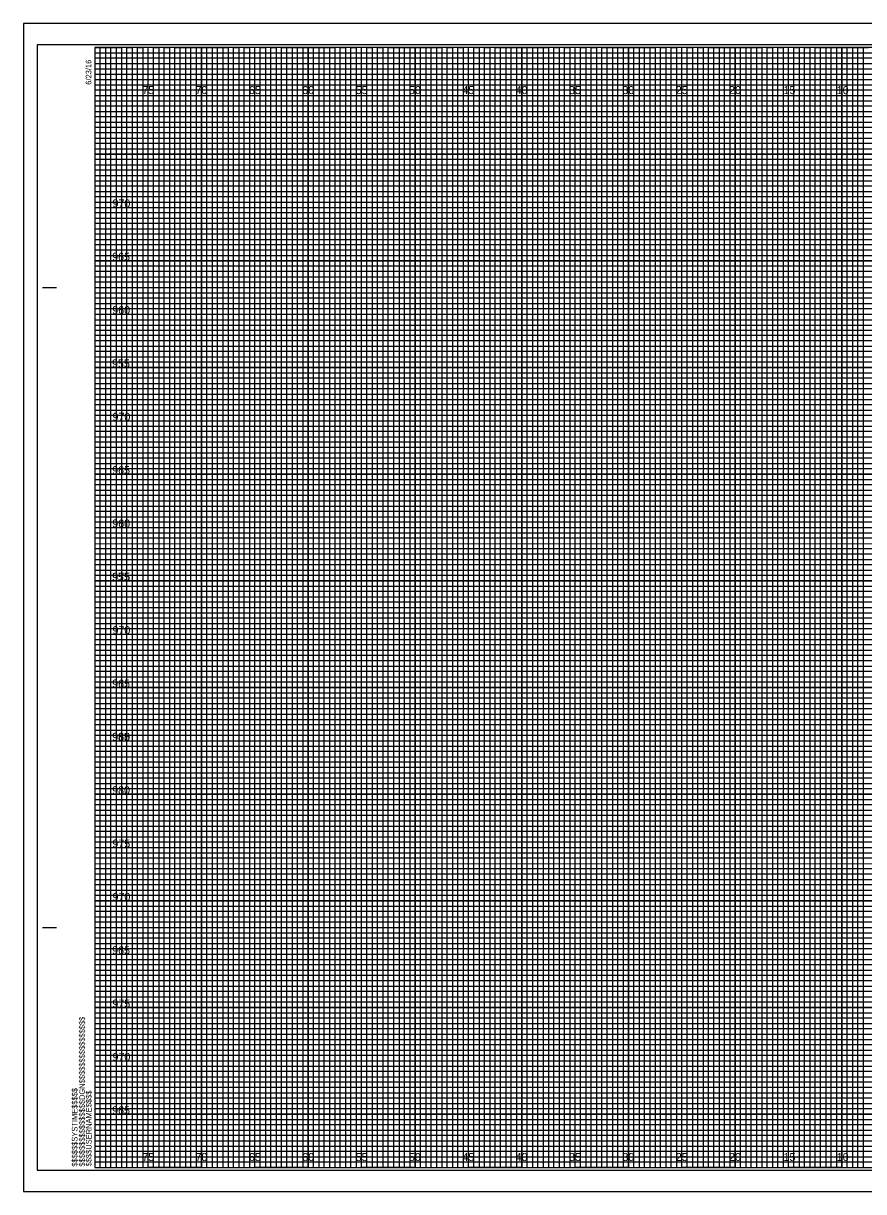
# Model space of a CAD drawing. Extents: x -7 to 162, y -2 to 107.
# Drawn here: x -6.7 to 72, y -2.3 to 107.3 of the extents above; entities that cross this region are included whole.
import ezdxf

# ---------------------------------------------------------------- set-up
doc = ezdxf.new("R2010")
doc.units = 0
for name, color, linetype in [('Prop XS Elevation Labels', 7, 'Continuous'), ('Prop XS Offset Labels', 7, 'Continuous'), ('Sheet Cross Section CELL', 7, 'Continuous'), ('Sheet Cross Section Grid Major CELL', 7, 'Continuous'), ('Sheet Cross Section Grid Middle CELL', 7, 'Continuous'), ('Sheet Cross Section Grid Minor 1 CELL', 7, 'Continuous'), ('Sheet Cross Section Grid Minor 2 CELL', 7, 'Continuous'), ('Sheet Cutting Line CELL', 7, 'Continuous'), ('Sheet DOT Grid CELL', 7, 'Continuous'), ('Sheet Plot Border Inside CELL', 7, 'Continuous'), ('Sheet Plot Border Outside CELL', 7, 'Continuous')]:
    doc.layers.add(name, color=color, linetype=linetype)

msp = doc.modelspace()

# ---------------------------------------------------------------- linework, layer by layer
at = {"layer": 'Sheet Cross Section CELL'}
for p, q in [((-4.9, 82.5), (-3.65, 82.5)), ((-4.85, 82.5), (-3.6, 82.5)), ((-4.9, 22.5), (-3.65, 22.5)), ((-4.85, 22.5), (-3.6, 22.5)), ((0, 0), (0, 0)), ((0, 0), (0, 0)), ((0, 0), (0, 0)), ((0, 0), (0, 0)), ((0, 0), (0, 0)), ((0, 0), (0, 0)), ((0, 0), (0, 0))]:
    msp.add_line(p, q, dxfattribs=at)
msp.add_lwpolyline([(160, 105), (0, 105), (0, 0), (160, 0)], close=True, dxfattribs=at)
at = {"layer": 'Sheet Cross Section Grid Major CELL'}
for p, q in [((5, 105), (0, 105)), ((5, 0), (5, 105)), ((15, 105), (10, 105)), ((10, 105), (10, 0)), ((15, 0), (15, 105)), ((25, 105), (20, 105)), ((20, 105), (20, 0)), ((25, 0), (25, 105)), ((35, 105), (30, 105)), ((30, 105), (30, 0)), ((35, 0), (35, 105)), ((45, 105), (40, 105)), ((40, 105), (40, 0)), ((45, 0), (45, 105)), ((55, 105), (50, 105)), ((50, 105), (50, 0)), ((55, 0), (55, 105)), ((65, 105), (60, 105)), ((60, 105), (60, 0)), ((65, 0), (65, 105)), ((75, 105), (70, 105)), ((70, 105), (70, 0)), ((10, 0), (5, 0)), ((20, 0), (15, 0)), ((30, 0), (25, 0)), ((40, 0), (35, 0)), ((50, 0), (45, 0)), ((60, 0), (55, 0)), ((70, 0), (65, 0))]:
    msp.add_line(p, q, dxfattribs=at)
for points in [[(0, 100), (160, 100), (160, 95), (0, 95)], [(0, 90), (160, 90), (160, 85), (0, 85)], [(0, 80), (160, 80), (160, 75), (0, 75)], [(0, 70), (160, 70), (160, 65), (0, 65)], [(0, 60), (160, 60), (160, 55), (0, 55)], [(0, 50), (160, 50), (160, 45), (0, 45)], [(0, 40), (160, 40), (160, 35), (0, 35)], [(0, 30), (160, 30), (160, 25), (0, 25)], [(0, 20), (160, 20), (160, 15), (0, 15)], [(0, 10), (160, 10), (160, 5), (0, 5)]]:
    msp.add_lwpolyline(points, dxfattribs=at)
at = {"layer": 'Sheet Cross Section Grid Middle CELL'}
for points in [[(0, 105), (2.5, 105), (2.5, 0), (7.5, 0), (7.5, 105), (12.5, 105), (12.5, 0), (17.5, 0), (17.5, 105), (22.5, 105), (22.5, 0), (27.5, 0), (27.5, 105), (32.5, 105), (32.5, 0), (37.5, 0), (37.5, 105), (42.5, 105), (42.5, 0), (47.5, 0), (47.5, 105), (52.5, 105), (52.5, 0), (57.5, 0), (57.5, 105), (62.5, 105), (62.5, 0), (67.5, 0), (67.5, 105), (72.5, 105)], [(0, 102.5), (137.5, 102.5)], [(0, 92.5), (160, 92.5), (160, 97.5), (0, 97.5)], [(0, 82.5), (160, 82.5), (160, 87.5), (0, 87.5)], [(0, 72.5), (160, 72.5), (160, 77.5), (0, 77.5)], [(0, 62.5), (160, 62.5), (160, 67.5), (0, 67.5)], [(0, 52.5), (160, 52.5), (160, 57.5), (0, 57.5)], [(0, 42.5), (160, 42.5), (160, 47.5), (0, 47.5)], [(0, 32.5), (160, 32.5), (160, 37.5), (0, 37.5)], [(0, 22.5), (160, 22.5), (160, 27.5), (0, 27.5)], [(0, 12.5), (160, 12.5), (160, 17.5), (0, 17.5)], [(0, 2.5), (160, 2.5), (160, 7.5), (0, 7.5)]]:
    msp.add_lwpolyline(points, dxfattribs=at)
at = {"layer": 'Sheet Cross Section Grid Minor 1 CELL'}
for p, q in [((0, 104.5), (130, 104.5)), ((130, 103.99), (0, 103.99)), ((0, 103.99), (0, 103.5)), ((0, 103.5), (130, 103.5)), ((130, 102.95), (0, 102.95)), ((0, 102.95), (0, 102)), ((0, 102), (160, 102))]:
    msp.add_line(p, q, dxfattribs=at)
for points in [[(0, 101.5), (135, 101.5), (160, 101.5), (160, 101), (0, 101)], [(0, 100.5), (160, 100.5), (160, 99.5), (0, 99.5)], [(0, 99), (160, 99), (160, 98.5), (0, 98.49)], [(0, 98), (160, 98), (160, 97), (0, 97)], [(0, 96.5), (160, 96.5), (160, 96), (0, 96)], [(0, 95.5), (160, 95.5), (160, 94.5), (0, 94.5)], [(0, 94), (160, 94), (160, 93.5), (0, 93.5)], [(0, 93), (160, 93), (160, 92), (0, 92)], [(0, 91.5), (160, 91.5), (160, 91), (0, 91)], [(0, 90.5), (160, 90.5), (160, 89.5), (0, 89.5)], [(0, 89), (160, 89), (160, 88.5), (0, 88.5)], [(0, 88), (160, 88), (160, 86.98), (160, 86.5), (160, 86), (0, 86)], [(0, 87), (160, 87), (160, 86.5), (0, 86.5)], [(0, 85.5), (160, 85.5), (160, 84.5), (0, 84.52)], [(0, 84.52), (160, 84.5), (160, 84), (0, 84)], [(0, 83.5), (160, 83.5), (160, 83), (0, 83)], [(0, 82), (160, 82), (160, 81.5), (0, 81.5)], [(0, 81), (160, 81), (160, 80.5), (0, 80.5)], [(-0.04, 79.45), (160, 79.45), (160, 78.94), (-0.04, 78.94)], [(0, 78.5), (160, 78.5), (160, 78), (0, 78)], [(0, 77), (160, 77), (160, 76.5), (0, 76.5)], [(0, 76), (160, 76), (160, 75.5), (0, 75.5)], [(0, 74.5), (160, 74.5), (160, 74), (0, 74)], [(0, 73.5), (160, 73.5), (160, 73), (0, 73)], [(0, 72), (160, 72), (160, 71.5), (0, 71.5)], [(0, 71), (160, 71), (160, 70.5), (0, 70.5)], [(0, 69.5), (160, 69.5), (160, 68.99), (0, 69)], [(0, 68.5), (160, 68.5), (160, 68), (0, 68)], [(0, 67), (160, 67), (160, 66.5), (0, 66.5)], [(0, 66), (160, 66), (160, 65.5), (0, 65.5)], [(0, 64.5), (160, 64.5), (160, 64), (0, 64)], [(0, 63.5), (160, 63.5), (160, 63), (0, 63)], [(0, 62), (160, 62), (160, 61.5), (0, 61.5)], [(0, 61), (160, 61), (160, 60.5), (0, 60.5)], [(0, 59.5), (160, 59.5), (160, 59), (0, 59)], [(0, 58.5), (160.03, 58.45), (160, 58), (0, 58)], [(0, 57), (160, 57), (160, 56.5), (0, 56.5)], [(0, 56), (160, 56), (160, 55.5), (0, 55.5)], [(0, 54.5), (160, 54.5), (160, 54), (0, 54)], [(0, 53.5), (160, 53.5), (160, 53), (0, 53)], [(0, 52), (160, 52), (160, 51.5), (0, 51.5)], [(0, 51), (160, 51), (160, 50.5), (0, 50.5)], [(0, 49.5), (160, 49.5), (160, 49), (0, 49)], [(0, 48.5), (160, 48.5), (160, 48), (0, 48)], [(0, 47), (160, 47), (160, 46.5), (0, 46.5)], [(0, 46), (160, 46), (160, 45.5), (0, 45.5)], [(0, 44.5), (160, 44.5), (160, 44), (0, 44)], [(0, 43.5), (160, 43.5), (160, 43), (0, 43)], [(0, 42), (160, 42), (160, 41.5), (0, 41.5)], [(0, 41), (160, 41), (160, 40.5), (0, 40.5)], [(0, 39.5), (160, 39.5), (160, 38.99), (0, 39)], [(0, 38.5), (160, 38.5), (160, 38), (0, 38)], [(0, 37), (160, 37), (160, 36.5), (0, 36.5)], [(0, 36), (160, 36), (160, 35.5), (0, 35.5)], [(0, 34.5), (160, 34.5), (160, 34), (0, 34)], [(0, 33.5), (160, 33.5), (160, 33), (0, 33)], [(0, 32), (160, 32), (160, 31.5), (0, 31.5)], [(0, 31), (160, 31), (160, 30.5), (0, 30.5)], [(0, 29.5), (160, 29.5), (160, 29), (0, 29)], [(0, 28.5), (160.03, 28.46), (160, 28), (0, 28)], [(0, 27), (160, 27), (160, 26.5), (0, 26.5)], [(0, 26), (160, 26), (160, 25.5), (0, 25.5)], [(0, 24.5), (160, 24.5), (160, 24), (0, 24)], [(0, 23.5), (160, 23.5), (160, 23), (0, 23)], [(0, 22), (160, 22), (160, 21.5), (0, 21.5)], [(0, 21), (160, 21), (160, 20.5), (0, 20.5)], [(0, 19.5), (160, 19.5), (160, 19), (0, 19)], [(0, 18.5), (160, 18.5), (160, 18), (0, 18)], [(0, 17), (160, 17), (160, 16.5), (0, 16.5)], [(0, 16), (160, 16), (160, 15.5), (0, 15.5)], [(0, 14.5), (160, 14.5), (160, 14), (0, 14)], [(0, 13.5), (160, 13.5), (160, 13), (0, 13)], [(0, 12), (160, 12), (160, 11.5), (0, 11.5)], [(0, 11), (160, 11), (160, 10.5), (0, 10.5)], [(0, 9.5), (160, 9.5), (160, 9), (0, 9)], [(0, 8.5), (160, 8.5), (160, 8), (0, 8)], [(0, 7), (160, 7), (160, 6.5), (0, 6.5)], [(0, 6), (160, 6), (160, 5.5), (0, 5.5)], [(0, 4.5), (160, 4.5), (160, 4), (0, 4)], [(0, 3.5), (160, 3.5), (160, 3), (0, 3)], [(0, 2), (160, 2), (160, 1.5), (0, 1.5)], [(0, 1), (160, 1), (160, 0.5), (0, 0.5)]]:
    msp.add_lwpolyline(points, dxfattribs=at)
at = {"layer": 'Sheet Cross Section Grid Minor 2 CELL'}
for points in [[(0, 0), (0.5, 0), (0.5, 105), (1, 105), (1, 0)], [(1, 0), (1.5, 0), (1.5, 105), (2, 105), (2, 0)], [(2.5, 0), (3, 0), (3, 105), (3.5, 105), (3.5, 0)], [(3.5, 0), (4, 0), (4, 105), (4.5, 105), (4.5, 0)], [(5, 0), (5.5, 0), (5.5, 105), (6, 105), (6, 0)], [(6, 0), (6.5, 0), (6.5, 105), (7, 105), (7, 0)], [(7.5, 0), (8, 0), (8, 105), (8.5, 105), (8.5, 0)], [(8.5, 0), (9, 0), (9, 105), (9.5, 105), (9.5, 0)], [(10, 0), (10.5, 0), (10.5, 105), (11, 105), (11, 0)], [(11, 0), (11.5, 0), (11.5, 105), (12, 105), (12, 0)], [(12.5, 0), (13, 0), (13, 105), (13.5, 105), (13.5, 0)], [(13.5, 0), (14, 0), (14, 105), (14.5, 105), (14.5, 0)], [(15, 0), (15.5, 0), (15.5, 105), (16, 105), (16, 0)], [(16, 0), (16.5, 0), (16.5, 105), (17, 105), (17, 0)], [(17.5, 0), (18, 0), (18, 105), (18.5, 105), (18.5, 0)], [(18.5, 0), (19, 0), (19, 105), (19.5, 105), (19.5, 0)], [(20, 0), (20.5, 0), (20.5, 105), (21, 105), (21, 0)], [(21, 0), (21.5, 0), (21.5, 105), (22, 105), (22, 0)], [(22.5, 0), (23, 0), (23, 105), (23.5, 105), (23.5, 0)], [(23.5, 0), (24, 0), (24, 105), (24.5, 105), (24.5, 0)], [(25, 0), (25.5, 0), (25.5, 105), (26, 105), (26, 0)], [(26, 0), (26.5, 0), (26.5, 105), (27, 105), (27, 0)], [(27.5, 0), (28, 0), (28, 105), (28.5, 105), (28.5, 0)], [(28.5, 0), (29, 0), (29, 105), (29.5, 105), (29.5, 0)], [(30, 0), (30.5, 0), (30.5, 105), (31, 105), (31, 0)], [(31, 0), (31.5, 0), (31.5, 105), (32, 105), (32, 0)], [(32.5, 0), (33, 0), (33, 105), (33.5, 105), (33.5, 0)], [(33.5, 0), (34, 0), (34, 105), (34.5, 105), (34.5, 0)], [(35, 0), (35.5, 0), (35.5, 105), (36, 105), (36, 0)], [(36, 0), (36.5, 0), (36.5, 105), (37, 105), (37, 0)], [(37.5, 0), (38, 0), (38, 105), (38.5, 105), (38.5, 0)], [(38.5, 0), (39, 0), (39, 105), (39.5, 105), (39.5, 0)], [(40, 0), (40.5, 0), (40.5, 105), (41, 105), (41, 0)], [(41, 0), (41.5, 0), (41.5, 105), (42, 105), (42, 0)], [(42.5, 0), (43, 0), (43, 105), (43.5, 105), (43.5, 0)], [(43.5, 0), (44, 0), (44, 105), (44.5, 105), (44.5, 0)], [(45, 0), (45.5, 0), (45.5, 105), (46, 105), (46, 0)], [(46, 0), (46.5, 0), (46.5, 105), (47, 105), (47, 0)], [(47.5, 0), (48, 0), (48, 105), (48.5, 105), (48.5, 0)], [(48.5, 0), (49, 0), (49, 105), (49.5, 105), (49.5, 0)], [(50, 0), (50.5, 0), (50.5, 105), (51, 105), (51, 0)], [(51, 0), (51.5, 0), (51.5, 105), (52, 105), (52, 0)], [(52.5, 0), (53, 0), (53, 105), (53.5, 105), (53.5, 0)], [(53.5, 0), (54, 0), (54, 105), (54.5, 105), (54.5, 0)], [(55, 0), (55.5, 0), (55.5, 105), (56, 105), (56, 0)], [(56, 0), (56.5, 0), (56.5, 105), (57, 105), (57, 0)], [(57.5, 0), (58, 0), (58, 105), (58.5, 105), (58.5, 0)], [(58.5, 0), (59, 0), (59, 105), (59.5, 105), (59.5, 0)], [(60, 0), (60.5, 0), (60.5, 105), (61, 105), (61, 0)], [(61, 0), (61.5, 0), (61.5, 105), (62, 105), (62, 0)], [(62.5, 0), (63, 0), (63, 105), (63.5, 105), (63.5, 0)], [(63.5, 0), (64, 0), (64, 105), (64.5, 105), (64.5, 0)], [(65, 0), (65.5, 0), (65.5, 105), (66, 105), (66, 0)], [(66, 0), (66.5, 0), (66.5, 105), (67, 105), (67, 0)], [(67.5, 0), (68, 0), (68, 105), (68.5, 105), (68.5, 0)], [(68.5, 0), (69, 0), (69, 105), (69.5, 105), (69.5, 0)], [(70, 0), (70.5, 0), (70.5, 105), (71, 105), (71, 0)], [(71, 0), (71.5, 0), (71.5, 105), (72, 105), (72, 0)]]:
    msp.add_lwpolyline(points, dxfattribs=at)
at = {"layer": 'Sheet Cutting Line CELL'}
for p, q in [((161.65, 107.25), (-6.7, 107.25)), ((-6.7, 107.25), (-6.7, -2.25)), ((-6.7, -2.25), (161.65, -2.25))]:
    msp.add_line(p, q, dxfattribs=at)
at = {"layer": 'Sheet DOT Grid CELL'}
for p, q in [((5, 0), (5, 105)), ((10, 0), (10, 105)), ((15, 0), (15, 105)), ((20, 0), (20, 105)), ((25, 0), (25, 105)), ((30, 0), (30, 105)), ((35, 0), (35, 105)), ((40, 0), (40, 105)), ((45, 0), (45, 105)), ((50, 0), (50, 105)), ((55, 0), (55, 105)), ((60, 0), (60, 105)), ((65, 0), (65, 105)), ((70, 0), (70, 105)), ((0, 100), (160, 100)), ((0, 95), (160, 95)), ((0, 90), (160, 90)), ((0, 85), (160, 85)), ((0, 80), (160, 80)), ((0, 75), (160, 75)), ((0, 70), (160, 70)), ((0, 65), (160, 65)), ((0, 60), (160, 60)), ((0, 55), (160, 55)), ((0, 50), (160, 50)), ((0, 45), (160, 45)), ((0, 40), (160, 40)), ((0, 35), (160, 35)), ((0, 30), (160, 30)), ((0, 25), (160, 25)), ((0, 20), (160, 20)), ((0, 15), (160, 15)), ((0, 10), (160, 10)), ((0, 5), (160, 5))]:
    msp.add_line(p, q, dxfattribs=at)
at = {"layer": 'Sheet Plot Border Inside CELL'}
msp.add_lwpolyline([(-5.4, -0.25), (161.2, -0.25), (161.2, 105.25), (-5.4, 105.25)], close=True, dxfattribs=at)
at = {"layer": 'Sheet Plot Border Outside CELL'}
msp.add_lwpolyline([(-6.7, -2.25), (161.65, -2.25), (161.65, 107.25), (-6.7, 107.25)], close=True, dxfattribs=at)

# ---------------------------------------------------------------- texts
at = {"layer": 'Prop XS Elevation Labels'}
for s, p in [('970', (1.65, 90)), ('965', (1.62, 85)), ('960', (1.63, 80)), ('955', (1.6, 75)), ('970', (1.65, 70)), ('965', (1.62, 65)), ('960', (1.63, 60)), ('955', (1.6, 55)), ('975', (1.64, 55)), ('970', (1.65, 50)), ('965', (1.62, 45)), ('985', (1.61, 40)), ('960', (1.63, 40)), ('980', (1.62, 35)), ('975', (1.64, 30)), ('970', (1.65, 25)), ('965', (1.62, 20)), ('975', (1.64, 15)), ('970', (1.65, 10)), ('965', (1.62, 5))]:
    msp.add_text(s, height=0.75, dxfattribs=at).set_placement(p)
at = {"layer": 'Prop XS Offset Labels'}
for s, p in [('75', (4.44, 100.62)), ('70', (9.43, 100.62)), ('65', (14.44, 100.62)), ('60', (19.43, 100.62)), ('55', (24.44, 100.62)), ('50', (29.43, 100.62)), ('45', (34.44, 100.62)), ('40', (39.43, 100.62)), ('35', (44.44, 100.62)), ('30', (49.43, 100.62)), ('25', (54.44, 100.62)), ('20', (59.43, 100.62)), ('15', (64.53, 100.62)), ('10', (69.52, 100.62)), ('75', (4.44, 0.62)), ('70', (9.43, 0.62)), ('65', (14.44, 0.62)), ('60', (19.43, 0.62)), ('55', (24.44, 0.62)), ('50', (29.43, 0.62)), ('45', (34.44, 0.62)), ('40', (39.43, 0.62)), ('35', (44.44, 0.62)), ('30', (49.43, 0.62)), ('25', (54.44, 0.62)), ('20', (59.43, 0.62)), ('15', (64.53, 0.62)), ('10', (69.52, 0.62))]:
    msp.add_text(s, height=0.75, dxfattribs=at).set_placement(p)
at = {"layer": 'Sheet Cross Section CELL'}
for s, p in [('6/23/16', (-0.33, 101.5)), ('$$$$$$$$$$$$$$$$DGN$$$$$$$$$$$$$$$$', (-0.94, 0.09)), ('$$$$$$SYSTIME$$$$$', (-1.63, 0.09)), ('$$$$USERNAME$$$$', (-0.31, 0.12))]:
    msp.add_text(s, height=0.525, rotation=90, dxfattribs=at).set_placement(p)

doc.saveas('drawing.dxf')
